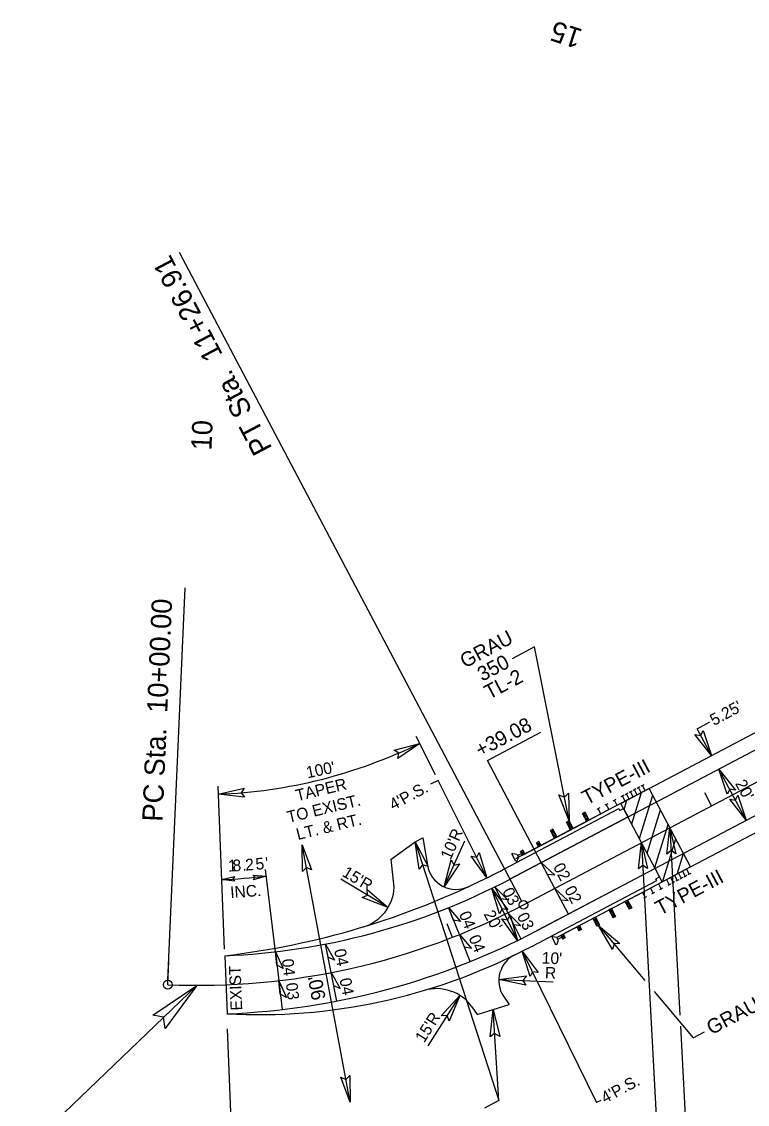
# Model space of a CAD drawing. Extents: x 1380803 to 1382221, y 595175 to 595787.
# Drawn here: x 1381403 to 1381652.6, y 595407.2 to 595779.7 of the extents above; entities that cross this region are included whole.
import ezdxf

# ---------------------------------------------------------------- set-up
doc = ezdxf.new("R2010")
doc.units = 0
for name, color, linetype in [('Prop Approach Slab', 7, 'Continuous'), ('Prop Approach Slab Hatching', 7, 'Continuous'), ('Prop DGN Element Guardrail', 7, 'Continuous'), ('Prop Dimension', 7, 'Continuous'), ('Prop Dimension Text', 7, 'Continuous'), ('Prop EOT', 7, 'Continuous'), ('Prop Guardrail', 7, 'Continuous'), ('Prop Guardrail Anchor Unit CELL', 7, 'Continuous'), ('Prop Horizontal Alignment', 7, 'Continuous'), ('Prop Horizontal Alignment Station Label', 7, 'Continuous'), ('Prop Horizontal Alignment Tick Large', 7, 'Continuous'), ('Prop Horizontal Alignment Tick Small', 7, 'Continuous'), ('Prop Paved Shoulder', 7, 'Continuous'), ('Prop Roadway Bridge', 7, 'Continuous'), ('Prop Shade Medium', 7, 'Continuous'), ('Prop Structure Anchor Unit CELL', 7, 'Continuous'), ('Prop Superelevation  Arrow CELL', 7, 'Continuous'), ('Prop Superelevation Label', 7, 'Continuous'), ('Prop Terminator CELL', 7, 'Continuous')]:
    doc.layers.add(name, color=color, linetype=linetype)

msp = doc.modelspace()

# ---------------------------------------------------------------- linework, layer by layer
at = {"layer": 'Prop Approach Slab'}
for p, q in [((1381609.09, 595510.73), (1381618.82, 595515.86)), ((1381633.05, 595488.88), (1381618.82, 595515.86)), ((1381623.32, 595483.75), (1381609.09, 595510.73)), ((1381623.32, 595483.75), (1381633.05, 595488.88))]:
    msp.add_line(p, q, dxfattribs=at)
at = {"layer": 'Prop Approach Slab Hatching'}
for p, q in [((1381612.82, 595503.66), (1381616.16, 595514.46)), ((1381615.46, 595498.65), (1381620.06, 595513.51)), ((1381610.18, 595508.66), (1381611.16, 595511.82)), ((1381618.1, 595493.65), (1381622.7, 595508.51)), ((1381620.73, 595488.65), (1381625.34, 595503.51)), ((1381623.37, 595483.64), (1381627.97, 595498.5)), ((1381628.43, 595486.44), (1381630.61, 595493.5))]:
    msp.add_line(p, q, dxfattribs=at)
at = {"layer": 'Prop DGN Element Guardrail'}
for p, q in [((1381618.82, 595515.86), (1381602.24, 595507.12)), ((1381602.24, 595507.12), (1381572.84, 595491.63)), ((1381633.05, 595488.88), (1381616.46, 595480.13)), ((1381616.46, 595480.13), (1381588.82, 595465.56))]:
    msp.add_line(p, q, dxfattribs=at)
at = {"layer": 'Prop Dimension'}
for p, q in [((1381635.29, 595536.43), (1381639.73, 595538.82)), ((1381640.27, 595527.17), (1381635.29, 595536.43)), ((1381545.27, 595520.57), (1381538.68, 595533.8)), ((1381563.16, 595525.54), (1381581.51, 595535.21)), ((1381581.7, 595490.36), (1381563.16, 595525.54)), ((1381652.23, 595504.93), (1381642.75, 595522.55)), ((1381470.42, 595516.67), (1381472.64, 595460.63)), ((1381546.22, 595518.65), (1381543.57, 595517.33)), ((1381562.93, 595485.1), (1381546.22, 595518.65)), ((1381515.98, 595407.98), (1381499.47, 595496.45)), ((1381538.3, 595497.47), (1381567.14, 595408.57)), ((1381548.31, 595482.01), (1381555.4, 595497.82)), ((1381529.01, 595474.9), (1381512.8, 595484.65)), ((1381564.7, 595481.51), (1381573.51, 595463.56)), ((1381575.16, 595459.87), (1381600.68, 595407.8)), ((1381567.11, 595450.16), (1381585.77, 595449.39)), ((1381553.69, 595444.66), (1381542.7, 595427.36)), ((1381567.14, 595408.57), (1381565.12, 595439.83)), ((1381475.64, 595387.03), (1381473.81, 595433.12)), ((1381567.14, 595408.57), (1381562.12, 595405.92)), ((1381602.17, 595408.52), (1381600.68, 595407.8))]:
    msp.add_line(p, q, dxfattribs=at)
msp.add_arc((1381463.64, 595687.36), 173.63, 272.2746, 296.0508, dxfattribs=at)
at = {"layer": 'Prop EOT'}
for p, q in [((1381570.94, 595484.68), (1381795.62, 595603.13)), ((1381580.27, 595466.99), (1381804.94, 595585.44)), ((1381472.81, 595458.32), (1381473.6, 595438.34))]:
    msp.add_line(p, q, dxfattribs=at)
for radius in [230, 250]:
    msp.add_arc((1381463.68, 595688.14), radius, 272.2746, 297.7977, dxfattribs=at)
at = {"layer": 'Prop Guardrail'}
for p, q in [((1381603.29, 595507.67), (1381597.76, 595504.76)), ((1381616.46, 595480.13), (1381610.93, 595477.22))]:
    msp.add_line(p, q, dxfattribs=at)
at = {"layer": 'Prop Guardrail Anchor Unit CELL'}
for p, q in [((1381579.35, 595564.54), (1381571.72, 595560.51)), ((1381591.26, 595504.76), (1381579.35, 595564.54)), ((1381596.79, 595507.67), (1381595.9, 595507.21)), ((1381597.32, 595504.52), (1381595.9, 595507.21)), ((1381595.9, 595507.21), (1381597.49, 595506.33)), ((1381596.61, 595505.87), (1381596.79, 595507.67)), ((1381597.49, 595506.33), (1381596.61, 595505.87)), ((1381598.2, 595504.99), (1381596.61, 595505.87)), ((1381598.2, 595504.99), (1381596.79, 595507.67)), ((1381597.49, 595506.33), (1381597.32, 595504.52)), ((1381575.65, 595493.1), (1381597.76, 595504.76)), ((1381585.73, 595501.84), (1381584.85, 595501.38)), ((1381585.55, 595500.04), (1381585.73, 595501.84)), ((1381587.15, 595499.16), (1381585.73, 595501.84)), ((1381591.26, 595504.76), (1381590.37, 595504.29)), ((1381591.79, 595501.61), (1381590.37, 595504.29)), ((1381590.37, 595504.29), (1381591.97, 595503.42)), ((1381591.08, 595502.95), (1381591.26, 595504.76)), ((1381591.97, 595503.42), (1381591.08, 595502.95)), ((1381592.67, 595502.07), (1381591.08, 595502.95)), ((1381592.67, 595502.07), (1381591.26, 595504.76)), ((1381591.97, 595503.42), (1381591.79, 595501.61)), ((1381592.67, 595502.07), (1381591.79, 595501.61)), ((1381598.2, 595504.99), (1381597.32, 595504.52)), ((1381586.26, 595498.69), (1381584.85, 595501.38)), ((1381584.85, 595501.38), (1381586.44, 595500.5)), ((1381586.44, 595500.5), (1381585.55, 595500.04)), ((1381587.15, 595499.16), (1381585.55, 595500.04)), ((1381586.44, 595500.5), (1381586.26, 595498.69)), ((1381587.15, 595499.16), (1381586.26, 595498.69)), ((1381575.38, 595494.67), (1381574.5, 595494.21)), ((1381575.38, 595494.67), (1381575.2, 595492.86)), ((1381576.09, 595493.33), (1381575.38, 595494.67)), ((1381580.91, 595497.59), (1381580.02, 595497.12)), ((1381580.73, 595495.78), (1381580.02, 595497.12)), ((1381581.62, 595496.24), (1381580.02, 595497.12)), ((1381580.91, 595497.59), (1381580.73, 595495.78)), ((1381581.62, 595496.24), (1381580.73, 595495.78)), ((1381581.62, 595496.24), (1381580.91, 595497.59)), ((1381571.89, 595493.48), (1381571.62, 595493.34)), ((1381572.98, 595490.74), (1381571.62, 595493.34)), ((1381571.89, 595493.48), (1381573.33, 595493.27)), ((1381573.26, 595490.88), (1381572.98, 595490.74)), ((1381573.9, 595492.19), (1381573.26, 595490.88)), ((1381573.33, 595493.27), (1381573.9, 595492.19)), ((1381573.56, 595492.83), (1381574.86, 595493.51)), ((1381575.2, 595492.87), (1381573.9, 595492.19)), ((1381575.2, 595492.86), (1381574.5, 595494.21)), ((1381576.09, 595493.33), (1381574.5, 595494.21)), ((1381576.09, 595493.33), (1381575.2, 595492.86)), ((1381588.82, 595465.56), (1381610.93, 595477.22)), ((1381611.37, 595477.45), (1381610.49, 595476.99)), ((1381610.49, 595476.99), (1381611.91, 595474.3)), ((1381612.08, 595476.11), (1381610.49, 595476.99)), ((1381611.37, 595477.45), (1381611.2, 595475.64)), ((1381612.08, 595476.11), (1381611.2, 595475.64)), ((1381611.37, 595477.45), (1381612.79, 595474.77)), ((1381611.91, 595474.3), (1381612.08, 595476.11)), ((1381605.85, 595474.54), (1381604.96, 595474.07)), ((1381604.96, 595474.07), (1381606.38, 595471.39)), ((1381606.55, 595473.2), (1381604.96, 595474.07)), ((1381605.85, 595474.54), (1381605.67, 595472.73)), ((1381606.55, 595473.2), (1381605.67, 595472.73)), ((1381605.67, 595472.73), (1381607.26, 595471.85)), ((1381605.85, 595474.54), (1381607.26, 595471.85)), ((1381606.38, 595471.39), (1381606.55, 595473.2)), ((1381611.2, 595475.64), (1381612.79, 595474.77)), ((1381612.79, 595474.77), (1381611.91, 595474.3)), ((1381594.79, 595468.71), (1381593.9, 595468.24)), ((1381593.9, 595468.24), (1381594.61, 595466.9)), ((1381595.5, 595467.37), (1381593.9, 595468.24)), ((1381594.79, 595468.71), (1381594.61, 595466.9)), ((1381594.79, 595468.71), (1381595.5, 595467.37)), ((1381600.32, 595471.62), (1381599.43, 595471.16)), ((1381599.43, 595471.16), (1381600.85, 595468.47)), ((1381601.02, 595470.28), (1381599.43, 595471.16)), ((1381600.32, 595471.62), (1381600.14, 595469.81)), ((1381601.02, 595470.28), (1381600.14, 595469.81)), ((1381600.14, 595469.81), (1381601.73, 595468.94)), ((1381600.32, 595471.62), (1381601.73, 595468.94)), ((1381600.85, 595468.47), (1381601.02, 595470.28)), ((1381601.73, 595468.94), (1381600.85, 595468.47)), ((1381601.42, 595468.68), (1381617.28, 595449.85)), ((1381607.26, 595471.85), (1381606.38, 595471.39)), ((1381585.64, 595464.84), (1381585.37, 595464.7)), ((1381585.37, 595464.7), (1381586.74, 595462.1)), ((1381587.08, 595464.63), (1381585.64, 595464.84)), ((1381588.38, 595465.32), (1381587.08, 595464.63)), ((1381587.65, 595463.55), (1381587.08, 595464.63)), ((1381587.42, 595463.99), (1381588.72, 595464.68)), ((1381589.26, 595465.79), (1381588.37, 595465.33)), ((1381588.37, 595465.33), (1381589.08, 595463.99)), ((1381589.97, 595464.45), (1381588.37, 595465.33)), ((1381589.26, 595465.79), (1381589.08, 595463.98)), ((1381589.26, 595465.79), (1381589.97, 595464.45)), ((1381595.5, 595467.37), (1381594.61, 595466.9)), ((1381587.01, 595462.24), (1381586.74, 595462.1)), ((1381587.01, 595462.24), (1381587.65, 595463.55)), ((1381589.97, 595464.45), (1381589.08, 595463.99)), ((1381620.54, 595445.99), (1381633.92, 595430.1)), ((1381633.92, 595430.1), (1381637.87, 595432.18))]:
    msp.add_line(p, q, dxfattribs=at)
for points in [[(1381591.01, 595514.27), (1381591.26, 595504.76), (1381587.78, 595513.68), (1381589.65, 595512.83)], [(1381606.22, 595460.47), (1381601.42, 595468.68), (1381608.77, 595462.54), (1381606.72, 595462.38)]]:
    msp.add_lwpolyline(points, close=True, dxfattribs=at)
at = {"layer": 'Prop Horizontal Alignment'}
msp.add_line((1381575.6, 595475.83), (1381800.28, 595594.28), dxfattribs=at)
msp.add_arc((1381463.68, 595688.14), 240, 267.4999, 297.7977, dxfattribs=at)
at = {"layer": 'Prop Horizontal Alignment Station Label'}
for p, q in [((1381574.9, 595477.16), (1381457.28, 595700.28)), ((1381453.27, 595449.87), (1381459.17, 595584.93)), ((1381625.94, 595502.37), (1381629.38, 595437.92)), ((1381616.2, 595497.24), (1381624.54, 595341.15)), ((1381463.21, 595448.14), (1381386.67, 595374.68)), ((1381629.58, 595434.06), (1381634.24, 595346.9))]:
    msp.add_line(p, q, dxfattribs=at)
for centre in [(1381575.6, 595475.83), (1381453.21, 595448.37)]:
    msp.add_circle(centre, 1.5, dxfattribs=at)
at = {"layer": 'Prop Horizontal Alignment Tick Large'}
msp.add_line((1381453.21, 595448.37), (1381453.56, 595456.36), dxfattribs=at)
at = {"layer": 'Prop Horizontal Alignment Tick Small'}
for p, q in [((1381640.26, 595509.92), (1381637.93, 595514.34)), ((1381551.14, 595464.64), (1381549.32, 595469.3))]:
    msp.add_line(p, q, dxfattribs=at)
at = {"layer": 'Prop Paved Shoulder'}
for p, q in [((1381569.07, 595488.22), (1381608.35, 595508.92)), ((1381538.3, 595497.47), (1381540.96, 595498.86)), ((1381540.96, 595498.86), (1381542.54, 595489.47)), ((1381530.11, 595491.55), (1381538.3, 595497.47)), ((1381531.13, 595481.8), (1381530.11, 595491.55)), ((1381582.13, 595463.45), (1381621.41, 595484.16)), ((1381568.67, 595444.38), (1381570.65, 595441.54)), ((1381557.85, 595440.72), (1381559.69, 595438.15)), ((1381559.69, 595438.15), (1381570.65, 595441.54))]:
    msp.add_line(p, q, dxfattribs=at)
for centre, radius, start, end in [((1381552.4, 595491.13), 10, 189.5716, 294.9307), ((1381463.68, 595688.14), 226, 296.1478, 297.7977), ((1381440.7, 595731.44), 275, 276.7048, 296.4698), ((1381516.15, 595482.63), 15, 286.8707, 356.8211), ((1381463.68, 595688.14), 254, 296.1478, 297.7977), ((1381484.26, 595638.05), 200, 266.9443, 297.1781), ((1381577.11, 595449.75), 10, 115.4453, 212.4676), ((1381545.65, 595432), 15, 35.5322, 106.5894)]:
    msp.add_arc(centre, radius, start, end, dxfattribs=at)
at = {"layer": 'Prop Roadway Bridge'}
for p, q in [((1381618.82, 595515.86), (1381704.97, 595561.27)), ((1381633.05, 595488.88), (1381719.19, 595534.29))]:
    msp.add_line(p, q, dxfattribs=at)
at = {"layer": 'Prop Shade Medium'}
for p, q in [((1381611.54, 595506.09), (1381570.94, 595484.68)), ((1381610.03, 595508.96), (1381611.54, 595506.09)), ((1381620.87, 595488.39), (1381580.27, 595466.99)), ((1381582.13, 595463.45), (1381621.41, 595484.16))]:
    msp.add_line(p, q, dxfattribs=at)
for points in [[(1381569.07, 595488.22), (1381608.35, 595508.92), (1381608.7, 595508.26), (1381610.03, 595508.96)], [(1381621.41, 595484.16), (1381621.06, 595484.82), (1381622.38, 595485.52), (1381620.87, 595488.39)]]:
    msp.add_lwpolyline(points, dxfattribs=at)
for centre, radius, start, end in [((1381463.68, 595688.14), 226, 296.1478, 297.7977), ((1381440.7, 595731.44), 275, 276.7048, 296.4698), ((1381463.68, 595688.14), 230, 272.2746, 297.7977), ((1381463.68, 595688.14), 250, 272.2746, 297.7977), ((1381463.68, 595688.14), 254, 296.1478, 297.7977), ((1381484.26, 595638.05), 200, 266.9443, 297.1781)]:
    msp.add_arc(centre, radius, start, end, dxfattribs=at)
at = {"layer": 'Prop Structure Anchor Unit CELL'}
for p, q in [((1381617.02, 595517.17), (1381616, 595516.63)), ((1381617.44, 595515.13), (1381616.51, 595516.9)), ((1381618.82, 595515.86), (1381602.24, 595507.12)), ((1381610.1, 595513.52), (1381609.09, 595512.99)), ((1381610.53, 595511.49), (1381609.6, 595513.26)), ((1381611.49, 595514.25), (1381610.47, 595513.72)), ((1381611.91, 595512.22), (1381610.98, 595513.99)), ((1381612.87, 595514.98), (1381611.86, 595514.45)), ((1381613.29, 595512.94), (1381612.36, 595514.71)), ((1381614.25, 595515.71), (1381613.24, 595515.18)), ((1381614.68, 595513.67), (1381613.74, 595515.44)), ((1381615.63, 595516.44), (1381614.62, 595515.9)), ((1381616.06, 595514.4), (1381615.13, 595516.17)), ((1381604.58, 595510.61), (1381603.56, 595510.07)), ((1381605, 595508.57), (1381604.07, 595510.34)), ((1381607.34, 595512.07), (1381606.33, 595511.53)), ((1381607.77, 595510.03), (1381606.83, 595511.8)), ((1381601.81, 595509.15), (1381600.8, 595508.62)), ((1381602.24, 595507.12), (1381601.3, 595508.88)), ((1381633.05, 595488.88), (1381616.46, 595480.13)), ((1381630.28, 595487.42), (1381631.22, 595485.65)), ((1381631.66, 595488.15), (1381632.6, 595486.38)), ((1381624.75, 595484.51), (1381625.69, 595482.74)), ((1381626.14, 595485.24), (1381627.07, 595483.47)), ((1381627.58, 595483.73), (1381626.56, 595483.2)), ((1381627.52, 595485.96), (1381628.45, 595484.2)), ((1381628.96, 595484.46), (1381627.94, 595483.93)), ((1381628.9, 595486.69), (1381629.83, 595484.92)), ((1381630.34, 595485.19), (1381629.33, 595484.66)), ((1381631.72, 595485.92), (1381630.71, 595485.39)), ((1381633.1, 595486.65), (1381632.09, 595486.11)), ((1381616.46, 595480.13), (1381617.39, 595478.37)), ((1381619.23, 595481.59), (1381620.16, 595479.82)), ((1381620.66, 595480.09), (1381619.65, 595479.56)), ((1381621.99, 595483.05), (1381622.92, 595481.28)), ((1381623.43, 595481.55), (1381622.42, 595481.01)), ((1381626.19, 595483), (1381625.18, 595482.47)), ((1381617.9, 595478.63), (1381616.89, 595478.1))]:
    msp.add_line(p, q, dxfattribs=at)
at = {"layer": 'Prop Superelevation  Arrow CELL'}
for points in [[(1381581.7, 595490.36), (1381586.31, 595486.02), (1381583.89, 595486.28)], [(1381565.75, 595482.03), (1381570.24, 595477.58), (1381567.84, 595477.9)], [(1381586.37, 595481.51), (1381590.97, 595477.17), (1381588.56, 595477.44)], [(1381549.8, 595474.87), (1381553.94, 595470.09), (1381551.56, 595470.6)], [(1381570.19, 595473.07), (1381574.68, 595468.61), (1381572.27, 595468.94)], [(1381553.54, 595465.6), (1381557.68, 595460.82), (1381555.31, 595461.32)], [(1381507.52, 595462.35), (1381510.62, 595456.85), (1381508.4, 595457.81)], [(1381490.24, 595459.68), (1381492.92, 595453.95), (1381490.77, 595455.08)], [(1381491.39, 595449.74), (1381494.07, 595444.01), (1381491.93, 595445.15)], [(1381509.42, 595452.54), (1381512.53, 595447.03), (1381510.31, 595448)]]:
    msp.add_lwpolyline(points, close=True, dxfattribs=at)
at = {"layer": 'Prop Superelevation Label'}
for p, q in [((1381490.24, 595459.68), (1381486.82, 595487.97)), ((1381586.37, 595481.51), (1381581.7, 595490.36)), ((1381565.75, 595482.03), (1381570.19, 595473.07)), ((1381591.03, 595472.66), (1381586.37, 595481.51)), ((1381553.54, 595465.6), (1381549.8, 595474.87)), ((1381570.19, 595473.07), (1381574.63, 595464.11)), ((1381557.29, 595456.32), (1381553.54, 595465.6)), ((1381509.42, 595452.54), (1381507.52, 595462.35)), ((1381490.24, 595459.68), (1381491.39, 595449.74)), ((1381491.39, 595449.74), (1381492.55, 595439.81)), ((1381511.33, 595442.72), (1381509.42, 595452.54))]:
    msp.add_line(p, q, dxfattribs=at)
msp.add_arc((1381463.64, 595687.36), 203, 272.274, 276.6309, dxfattribs=at)
at = {"layer": 'Prop Terminator CELL'}
for points in [[(1381637.37, 595535.83), (1381640.27, 595527.17), (1381634.57, 595534.38), (1381636.53, 595534.12)], [(1381531.07, 595528.99), (1381539.89, 595531.37), (1381532.35, 595526.12), (1381532.72, 595528.05)], [(1381645.65, 595513.88), (1381642.75, 595522.55), (1381648.45, 595515.33), (1381646.5, 595515.59)], [(1381479.6, 595512.82), (1381470.53, 595513.87), (1381479.48, 595515.97), (1381478.42, 595514.31)], [(1381649.33, 595513.59), (1381652.23, 595504.93), (1381646.53, 595512.14), (1381648.49, 595511.89)], [(1381624.87, 595493.3), (1381625.94, 595502.37), (1381628.02, 595493.42), (1381626.36, 595494.48)], [(1381499.59, 595487.32), (1381499.47, 595496.45), (1381502.7, 595487.85), (1381500.92, 595488.68)], [(1381539.66, 595488.05), (1381538.3, 595497.47), (1381542.79, 595489.02), (1381540.84, 595489.64)], [(1381615.14, 595488.17), (1381616.2, 595497.24), (1381618.28, 595488.29), (1381616.63, 595489.35)], [(1381553.62, 595489.9), (1381548.31, 595482.01), (1381550.65, 595491.29), (1381551.68, 595489.51)], [(1381560.39, 595493.87), (1381562.93, 595485.1), (1381557.54, 595492.54), (1381559.48, 595492.2)], [(1381476.23, 595483.99), (1381471.69, 595484.52), (1381476.17, 595485.57), (1381475.64, 595484.74)], [(1381482.52, 595486.01), (1381487.08, 595485.72), (1381482.67, 595484.44), (1381483.15, 595485.3)], [(1381521.81, 595481.12), (1381529.01, 595474.9), (1381520.08, 595478.33), (1381521.96, 595479.14)], [(1381567.37, 595472.77), (1381564.7, 595481.51), (1381570.21, 595474.15), (1381568.26, 595474.45)], [(1381570.97, 595472.33), (1381573.51, 595463.56), (1381568.12, 595471), (1381570.06, 595470.66)], [(1381577.83, 595451.14), (1381575.16, 595459.87), (1381580.67, 595452.51), (1381578.72, 595452.82)], [(1381576.41, 595448.16), (1381567.11, 595450.16), (1381576.6, 595451.44), (1381575.33, 595449.82)], [(1381448.07, 595437.91), (1381463.21, 595448.14), (1381452.36, 595433.3), (1381451.81, 595437.2)], [(1381547.3, 595437.61), (1381553.69, 595444.66), (1381550.04, 595435.81), (1381549.28, 595437.72)], [(1381564.11, 595430.38), (1381565.12, 595439.83), (1381567.39, 595430.54), (1381565.65, 595431.62)], [(1381515.86, 595417.11), (1381515.98, 595407.98), (1381512.75, 595416.58), (1381514.53, 595415.74)]]:
    msp.add_lwpolyline(points, close=True, dxfattribs=at)

# ---------------------------------------------------------------- texts
at = {"layer": 'Prop Dimension'}
for s, rotation, p in [("5.25'", 28.2777, (1381641.08, 595537.34)), ("100'", 11.7455, (1381501.29, 595519.35)), ('TAPER', 13.6105, (1381497.74, 595511.43)), ("4'P.S.", 28.2777, (1381530.79, 595508.25)), ("20'", 298.2777, (1381648.25, 595517.61)), ('TO EXIST.', 13.6105, (1381494.78, 595504.02)), ('LT. & RT.', 13.6105, (1381497.96, 595498.1)), ("10'R", 65.8536, (1381550.48, 595491.04)), ("15'R", 329.0078, (1381512.91, 595485.94)), ("20'", 298.3227, (1381561.77, 595472.67)), ("10'", 357.6388, (1381581.81, 595455.65)), ('R', 357.6388, (1381582.89, 595450.53)), ("15'R", 57.5699, (1381541.39, 595428.1)), ("4'P.S.", 28.2777, (1381603.61, 595407.4))]:
    msp.add_text(s, height=4, rotation=rotation, dxfattribs=at).set_placement(p)
at = {"layer": 'Prop Dimension Text'}
for s, height, rotation, p in [('+39.08', 5, 27.7977, (1381560.7, 595526.55)), ("90'", 4.8, 100.5754, (1381507.6, 595443.55))]:
    msp.add_text(s, height=height, rotation=rotation, dxfattribs=at).set_placement(p)
at = {"layer": 'Prop Guardrail Anchor Unit CELL'}
for s, p in [('GRAU', (1381555.42, 595557.14)), ('350', (1381561.37, 595552.56)), ('TL-2', (1381563.75, 595546.36)), ('GRAU 350 TL-2', (1381640.22, 595430.96))]:
    msp.add_text(s, height=5, rotation=27.7977, dxfattribs=at).set_placement(p)
at = {"layer": 'Prop Horizontal Alignment Station Label'}
for s, rotation, p in [('15', 162.1091, (1381596.25, 595776.87)), ('PT Sta.  11+26.91', 117.7977, (1381489.28, 595632.89)), ('10', 87.4999, (1381468.23, 595632.04)), ('PC Sta.  10+00.00', 87.4999, (1381451.41, 595504.34))]:
    msp.add_text(s, height=7, rotation=rotation, dxfattribs=at).set_placement(p)
at = {"layer": 'Prop Structure Anchor Unit CELL'}
for p in [(1381597.35, 595510.05), (1381622.58, 595472.09)]:
    msp.add_text('TYPE-III', height=5, rotation=27.7977, dxfattribs=at).set_placement(p)
at = {"layer": 'Prop Superelevation Label'}
for s, rotation, p in [('1', 2.4993, (1381474.04, 595487.26)), ('8', 2.9493, (1381475.61, 595487.33)), ('2', 4.2091, (1381480.01, 595487.59)), ('5', 5.2351, (1381483.59, 595487.87)), ("'", 6.2251, (1381487.04, 595488.2)), ('.', 3.9033, (1381478.94, 595487.52)), ('02', 298.2777, (1381585.65, 595488.92)), ('INC.', 4.3049, (1381474.86, 595478.11)), ('03', 296.8258, (1381568.18, 595480.52)), ('02', 298.2777, (1381589.51, 595481.06)), ('04', 292.469, (1381553.31, 595472.66)), ('03', 296.8258, (1381573.23, 595471.96)), ('04', 292.469, (1381556.64, 595464.52)), ('04', 276.6314, (1381492.46, 595457.06)), ('04', 280.9883, (1381510.42, 595460.31)), ('EXIST', 92.2746, (1381478.85, 595439.55)), ('04', 280.9883, (1381512.28, 595450.28)), ('03', 276.6314, (1381493.84, 595448.84))]:
    msp.add_text(s, height=4, rotation=rotation, dxfattribs=at).set_placement(p)

doc.saveas('drawing.dxf')
